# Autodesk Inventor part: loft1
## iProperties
Shininess: 64.0
Length Units: 11269
Angle Units: 11279
Time Units: 11290
Mass Units: 11283
Length Display Precision: 3
Angle Display Precision: 2
Compacted: True
Part Number: loft1
Document SubType Name: Modeling
Created: 2002-12
Designer: deepak
Density: 1 g/cm^3
Density: 0.0
Volumn: 0.0
Area: 0.0
PropertySet Name: Model Information
Control State: 0
Master: False
Checked Out: False
Author: deepak
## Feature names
1. Loft3
